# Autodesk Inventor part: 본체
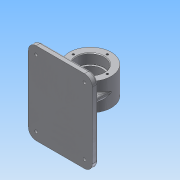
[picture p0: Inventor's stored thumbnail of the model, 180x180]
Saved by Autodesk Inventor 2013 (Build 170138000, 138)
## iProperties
Created: 2019-09
Part Number: 본체
Material: 알루미늄 6061
Document SubType Name: Modeling
Designer: Administrator
Density: 2.71 g/cm^3
Mass: 556.675 g
Surface Area: 495.884 cm^2
Volume: 205.415 cm^3
Author: Administrator
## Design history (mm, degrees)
sketch "스케치1"
  geometry: C1 r 32 at (0, 0); 1 further point
  constraints: 1 centre point, 1 coincident
  dimensions: "d0" = 64 diameter of C1
extrude "돌출1" new body sketch "스케치1" stored distance "d1" = 42; taper "d2" = 0 deg
sketch "스케치2"
  geometry: C1 r 32 at (0, 0) reference; C2 r 21 at (0, 0)
  constraints: 1 centre point, 1 coincident
  dimensions: "d3" = 42 diameter of C2
extrude "돌출2" cut sketch "스케치2" distance "d4" = 15; taper "d5" = 0 deg
hole "구멍1" diameter "d8" = 36; stored, may be unused: countersink angle "d12" = 90 deg, drill point angle "d14" = 0 deg; dims "d6" = 10, "d7" = 10, "d9" = 6, "d10" = 42, "d11" = 15, "d13" = 8
sketch "스케치3"
  geometry: C1 r 21 at (0, 0) reference; 1 further point
  constraints: 1 vertical alignment
  dimensions: "d15" = 26 distance of C1.centre point (0, 26)
hole "구멍2" sketch "스케치3" at (0, 26) diameter "d16" = 3.242; stored, may be unused: countersink angle "d20" = 90 deg, drill point angle "d22" = 118 deg; dims "d17" = 8, "d18" = 42, "d19" = 15, "d21" = 10
node "작업 평면1"
sketch "스케치4"
  geometry: L1 (-36, 63)-(62, 63); L2 (62, 63)-(62, -63); L3 (62, -63)-(-36, -63); L4 (-36, -63)-(-36, 63); 1 further point
  constraints: 8 end point, 2 parallel, 1 horizontal, 1 perpendicular
  dimensions: "d27" = 98 distance of L1.start L1.end; "d29" = 126 distance of L3.end L1.start; "d30" = 62 distance from line of L2 point (0, 0); "d31" = 63 distance from line of L3 point (0, 0)
extrude "돌출3" join sketch "스케치4" distance "d32" = 9; taper "d33" = 0 deg
sketch "스케치5"
  geometry: L1 (32, 4)-(-32, 4); L2 (-32, 4)-(-32, -4); L3 (-32, -4)-(32, -4); L4 (32, -4)-(32, 4); L5 (4, 17)-(-4, 17); L6 (-4, 17)-(-4, -17); L7 (-4, -17)-(4, -17); L8 (4, -17)-(4, 17); 5 further points
  constraints: 16 end point, 4 midpoint, 4 parallel, 2 horizontal, 2 horizontal alignment, 2 perpendicular, 2 vertical alignment
  dimensions: "d34" = 8 distance of L3.end L1.start; "d36" = 8 distance of L5.start L5.end; "d37" = 34 distance of L5.end L6.end; "d38" = 64 distance of L1.start L1.end
extrude "돌출4" join sketch "스케치5" stored distance "d39" = 9; taper "d40" = 0 deg
fillet "모깎기1" dims "d41" = 12
sketch "스케치6"
  geometry: A1 r 12 centre (50, 51) between (62, 51) and (50, 63) reference; A2 r 12 centre (-24, 51) between (-24, 63) and (-36, 51) reference; 3 further points
  constraints: 2 coincident
hole "구멍3" sketch "스케치6" at (-24, 51), (50, 51) diameter "d42" = 4.5; stored, may be unused: countersink angle "d46" = 90 deg, drill point angle "d48" = 0 deg; dims "d43" = 8, "d44" = 8, "d45" = 4.4, "d47" = 10
fillet "모깎기2" dims "d49" = 0.3
chamfer "모따기1" distance "d50" = 1; stored, may be unused: second distance "d51" = 2, angle "d52" = 45 deg
fillet "모깎기3" dims "d53" = 3
fillet "모깎기4" dims "d54" = 3
fillet "모깎기5" dims "d55" = 3
sketch "스케치7"
  geometry: L1 (62, -51)-(62, 51) reference; 2 further points
  constraints: 1 horizontal alignment, 1 other
  dimensions: "d56" = 10 distance from line of point (52, 0) L1
feature "엠보싱1" sketch "스케치7" dims "d57" = 0.5, "d58" = 0
node "솔리드1"
pattern_circular "원형 패턴1" dims angle "d24" = 360 deg
mirror "대칭1"
mirror "대칭2"
other parameters: "d26" = -59
